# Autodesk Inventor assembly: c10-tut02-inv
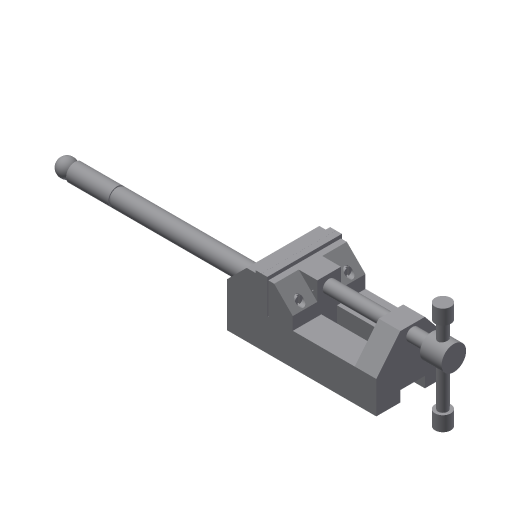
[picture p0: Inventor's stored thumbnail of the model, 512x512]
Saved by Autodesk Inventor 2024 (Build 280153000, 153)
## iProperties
Created: 2009-05
Part Number: c10-tut02-inv
Document SubType Name: Assembly
Designer: Sham
Author: Sham
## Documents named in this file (9)
- D:\PROJECTS\Project 2023\RESOURCES INVENTOR 2024\RESOURCES INVENTOR 2024\Inventor_2024_tut\Inventor_2024_tut\c10_Inv_2024_tut\c10_Inv_tut_2024\c10_tut02_inv\Drill Press Vice\Drill Press Vice Assembly.iam
- D:\PROJECTS\Project 2023\RESOURCES INVENTOR 2024\RESOURCES INVENTOR 2024\Inventor_2024_tut\Inventor_2024_tut\c10_Inv_2024_tut\c10_Inv_tut_2024\c10_tut02_inv\Drill Press Vice\Base.ipt
- D:\PROJECTS\Project 2023\RESOURCES INVENTOR 2024\RESOURCES INVENTOR 2024\Inventor_2024_tut\Inventor_2024_tut\c10_Inv_2024_tut\c10_Inv_tut_2024\c10_tut02_inv\Drill Press Vice\Safety Handle.ipt
- D:\PROJECTS\Project 2023\RESOURCES INVENTOR 2024\RESOURCES INVENTOR 2024\Inventor_2024_tut\Inventor_2024_tut\c10_Inv_2024_tut\c10_Inv_tut_2024\c10_tut02_inv\Drill Press Vice\Jaw Face.ipt
- D:\PROJECTS\Project 2023\RESOURCES INVENTOR 2024\RESOURCES INVENTOR 2024\Inventor_2024_tut\Inventor_2024_tut\c10_Inv_2024_tut\c10_Inv_tut_2024\c10_tut02_inv\Drill Press Vice\Movable Jaw.ipt
- D:\PROJECTS\Project 2023\RESOURCES INVENTOR 2024\RESOURCES INVENTOR 2024\Inventor_2024_tut\Inventor_2024_tut\c10_Inv_2024_tut\c10_Inv_tut_2024\c10_tut02_inv\Drill Press Vice\Cap Screw.ipt
- D:\PROJECTS\Project 2023\RESOURCES INVENTOR 2024\RESOURCES INVENTOR 2024\Inventor_2024_tut\Inventor_2024_tut\c10_Inv_2024_tut\c10_Inv_tut_2024\c10_tut02_inv\Drill Press Vice\Clamp Screw Handle.ipt
- D:\PROJECTS\Project 2023\RESOURCES INVENTOR 2024\RESOURCES INVENTOR 2024\Inventor_2024_tut\Inventor_2024_tut\c10_Inv_2024_tut\c10_Inv_tut_2024\c10_tut02_inv\Drill Press Vice\Clamp Screw.ipt
- D:\PROJECTS\Project 2023\RESOURCES INVENTOR 2024\RESOURCES INVENTOR 2024\Inventor_2024_tut\Inventor_2024_tut\c10_Inv_2024_tut\c10_Inv_tut_2024\c10_tut02_inv\Drill Press Vice\Handle Stop.ipt
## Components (11 placed, 8 different names)
1. Base:1 — Mate:1, Flush:1, Insert:1, Insert:2, Insert:3
2. Movable Jaw:1 — Mate:1, Flush:1, Insert:4, Insert:5, Insert:6, Insert:7, Insert:8
3. Safety Handle:1 — Insert:1
4. Jaw Face:1 — Insert:4, Insert:5, Mate:7
5. Jaw Face:2 — Insert:2, Insert:3, Mate:7
6. Cap Screw:1 — Insert:7
7. Cap Screw:2 — Insert:6
8. Clamp Screw:1 — Insert:8, Mate:2
9. Clamp Screw Handle:1 — Mate:2, Insert:9, Insert:10
10. Handle Stop:1 — Insert:10
11. Handle Stop:2 — Insert:9
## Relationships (14: Insert 10, Mate 3, Flush 1)
- Mate:1: Base:1 ↔ Movable Jaw:1
- Flush:1: Base:1 ↔ Movable Jaw:1
- Insert:1: Base:1 ↔ Safety Handle:1
- Insert:2: Base:1 ↔ Jaw Face:2
- Insert:3: Base:1 ↔ Jaw Face:2
- Insert:4: Movable Jaw:1 ↔ Jaw Face:1
- Insert:5: Movable Jaw:1 ↔ Jaw Face:1
- Insert:6: Movable Jaw:1 ↔ Cap Screw:2
- Insert:7: Movable Jaw:1 ↔ Cap Screw:1
- Insert:8: Movable Jaw:1 ↔ Clamp Screw:1
- Mate:2: Clamp Screw:1 ↔ Clamp Screw Handle:1
- Insert:9: Clamp Screw Handle:1 ↔ Handle Stop:2
- Insert:10: Clamp Screw Handle:1 ↔ Handle Stop:1
- Mate:7: Jaw Face:1 ↔ Jaw Face:2
